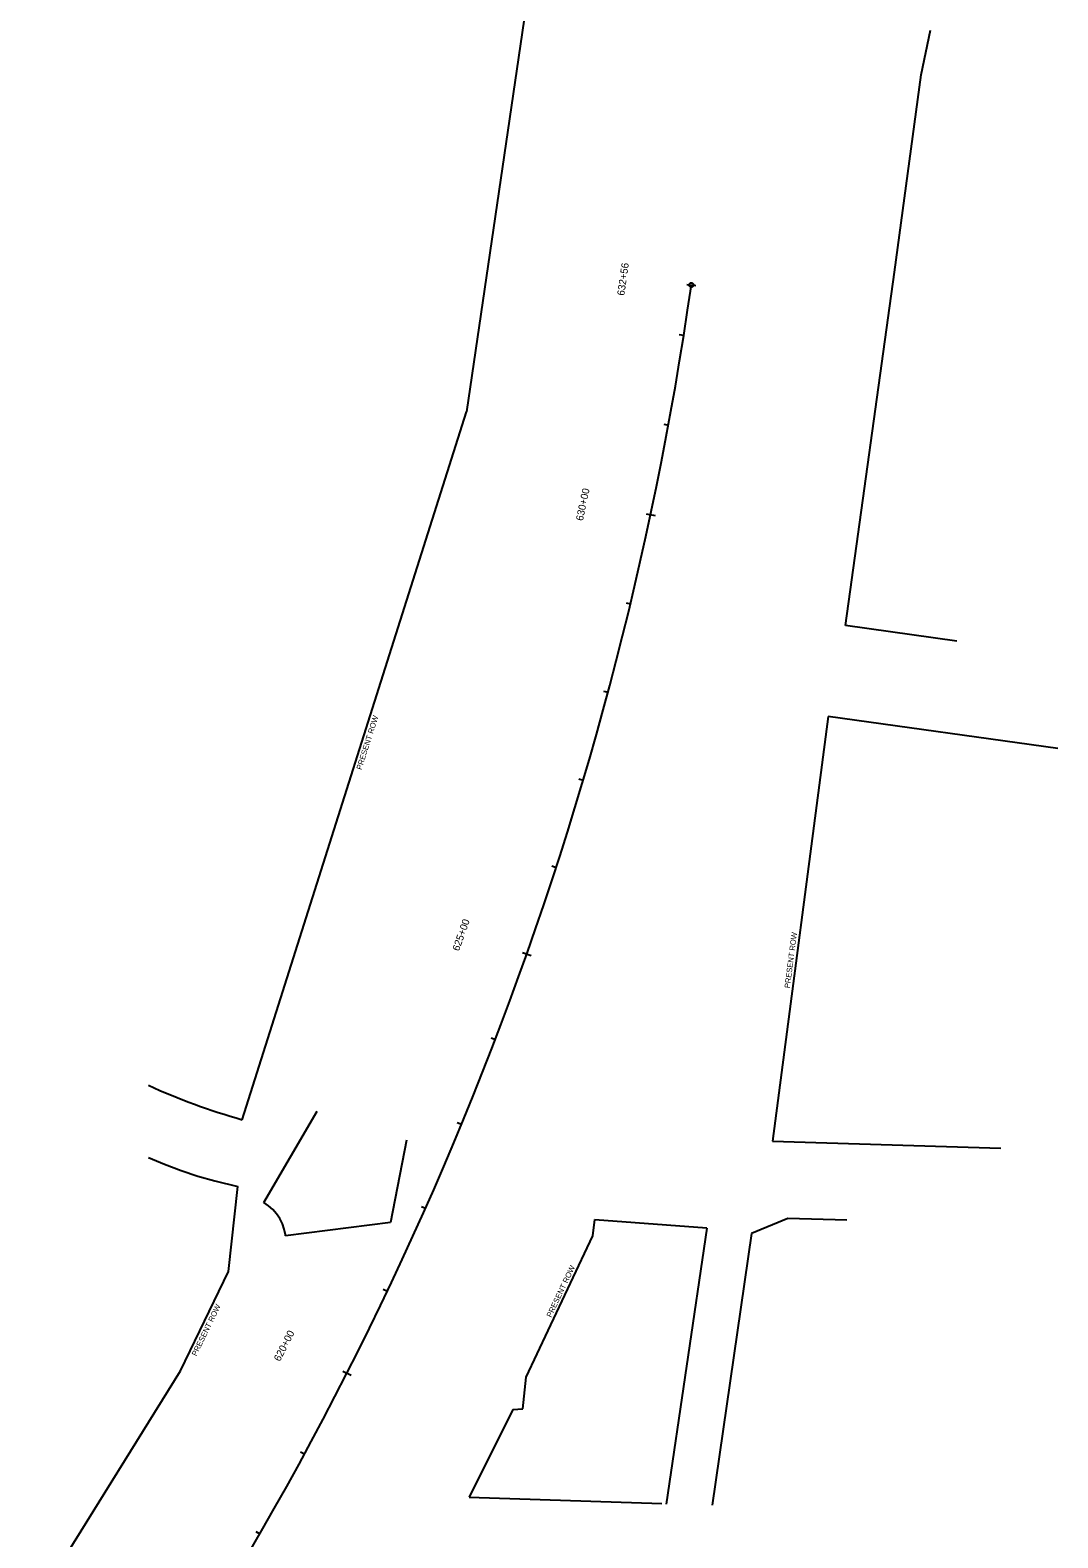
# Model space of a CAD drawing. Extents: x 1790419 to 1799551, y 243603 to 252255.
# Drawn here: x 1796886 to 1798012, y 245321 to 246972 of the extents above; entities that cross this region are included whole.
import ezdxf

# ---------------------------------------------------------------- set-up
doc = ezdxf.new("R2010")
doc.units = 0
for name, color, linetype in [('CL-CNST', 7, 'Continuous'), ('CL-CNSTTXT', 7, 'Continuous'), ('Default', 7, 'Continuous'), ('Level 1', 7, 'Continuous'), ('Prop_Horiz Alignment', 7, 'Continuous'), ('PRP_ROW', 7, 'Continuous'), ('PRPROWTXT', 7, 'Continuous'), ('Survey BL', 7, 'Continuous')]:
    doc.layers.add(name, color=color, linetype=linetype)

msp = doc.modelspace()

# ---------------------------------------------------------------- linework, layer by layer
at = {"layer": 'CL-CNST'}
for points in [[(1797605.5, 246693.2), (1797615.4, 246691.8)], [(1797597.3, 246638.4), (1797602.2, 246637.7)], [(1797580.4, 246540), (1797585.3, 246539.1)], [(1797561, 246442), (1797570.7, 246440)], [(1797539, 246344.6), (1797543.8, 246343.5)], [(1797514.4, 246247.8), (1797519.3, 246246.5)], [(1797487.4, 246151.7), (1797492.1, 246150.3)], [(1797457.8, 246056.3), (1797462.5, 246054.8)], [(1797425.7, 245961.7), (1797435.1, 245958.4)], [(1797391.2, 245868), (1797395.9, 245866.2)], [(1797354.2, 245775.3), (1797358.8, 245773.4)], [(1797314.8, 245683.5), (1797319.4, 245681.5)], [(1797273.1, 245592.8), (1797277.6, 245590.6)], [(1797228.9, 245503.2), (1797237.8, 245498.7)], [(1797182.5, 245414.8), (1797186.9, 245412.4)], [(1797133.7, 245327.6), (1797138, 245325.1)]]:
    msp.add_lwpolyline(points, dxfattribs=at)
at = {"layer": 'Default'}
msp.add_arc((1793829.3, 247233.7), 3819.7, 325.0377, 351.8556, dxfattribs=at)
at = {"layer": 'Level 1'}
for p, q in [((1797142.2, 245687.8), (1797200.7, 245787.8)), ((1797298.6, 245756), (1797281.2, 245665.9)), ((1797147.4, 245684.3), (1797142.2, 245687.8)), ((1797152.1, 245680.1), (1797147.4, 245684.3)), ((1797156.2, 245675.4), (1797152.1, 245680.1)), ((1797159.8, 245670.2), (1797156.2, 245675.4)), ((1797162.6, 245664.6), (1797159.8, 245670.2)), ((1797164.7, 245658.6), (1797162.6, 245664.6)), ((1797281.2, 245665.9), (1797166.2, 245651.3)), ((1797166, 245652.5), (1797164.7, 245658.6)), ((1797166.2, 245651.3), (1797166, 245652.5))]:
    msp.add_line(p, q, dxfattribs=at)
at = {"layer": 'Prop_Horiz Alignment'}
msp.add_circle((1797610.5, 246692.5), 2.5, dxfattribs=at)
at = {"layer": 'PRP_ROW'}
for p, q in [((1797488, 247396.5), (1797364.2, 246553.6)), ((1797862.2, 246922.6), (1797872.5, 246971.5)), ((1797832.8, 246706.6), (1797862.2, 246922.6)), ((1797779.4, 246319.7), (1797832.8, 246706.6)), ((1797118.5, 245778.4), (1797364.2, 246553.6)), ((1797901.2, 246302.4), (1797779.4, 246319.7)), ((1797760.2, 246219.8), (1797699.5, 245754.8)), ((1798011.8, 246185.1), (1797760.2, 246219.8)), ((1797699.5, 245754.8), (1797949.2, 245747.3)), ((1797016, 245737.2), (1797033.7, 245729.7)), ((1797033.7, 245729.7), (1797051.7, 245722.9)), ((1797051.7, 245722.9), (1797070, 245716.8)), ((1797070, 245716.8), (1797088.5, 245711.5)), ((1797088.5, 245711.5), (1797113.9, 245705.4)), ((1797103.5, 245612.1), (1797113.9, 245705.4)), ((1797502.7, 245651.3), (1797504.6, 245669.1)), ((1797504.6, 245669.1), (1797627.4, 245659.9)), ((1797716.3, 245670.3), (1797676.5, 245653.9)), ((1797780.7, 245668.3), (1797716.3, 245670.3)), ((1797453.8, 245547.7), (1797502.7, 245651.3)), ((1797627.3, 245659.8), (1797583, 245357.5)), ((1797676.5, 245653.9), (1797633.2, 245356.4)), ((1797050.9, 245503.6), (1797103.5, 245612.1)), ((1797429.7, 245496.7), (1797453.8, 245547.7)), ((1796886.4, 245238.3), (1797050.9, 245503.6)), ((1797425.9, 245461.7), (1797429.7, 245496.7)), ((1797414.9, 245461.2), (1797367, 245365.1)), ((1797414.9, 245461.2), (1797425.9, 245461.7)), ((1797425.9, 245461.7), (1797425.9, 245461.7)), ((1797367, 245365.1), (1797578.2, 245358.3))]:
    msp.add_line(p, q, dxfattribs=at)
msp.add_arc((1797311.6, 246463.3), 711.5, 245.4463, 254.2546, dxfattribs=at)
at = {"layer": 'Survey BL'}
msp.add_arc((1793829.3, 247233.7), 3819.7, 325.0377, 351.8556, dxfattribs=at)

# ---------------------------------------------------------------- texts
at = {"layer": 'CL-CNSTTXT'}
for s, rotation, p in [('632+56', 81.8556, (1797537, 246680.5)), ('630+00', 78.023, (1797491.7, 246433.7)), ('625+00', 70.523, (1797356, 245962.5)), ('620+00', 63.023, (1797159.9, 245513.1))]:
    msp.add_text(s, height=8, rotation=rotation, dxfattribs=at).set_placement(p)
at = {"layer": 'PRPROWTXT'}
for rotation, p in [(72.4091, (1797249.2, 246161.1)), (82.5572, (1797718.3, 245922.2)), (64.7331, (1797457, 245561.4)), (64.1332, (1797068.4, 245519.1))]:
    msp.add_text('PRESENT ROW', height=6, rotation=rotation, dxfattribs=at).set_placement(p)

doc.saveas('drawing.dxf')
